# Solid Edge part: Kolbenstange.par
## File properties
Username: bmolnar
Dokumentum tartalom típus: 0
Author: bmolnar
Last saved by: bmolnar
Revision: 82
Sűrűség: 0,000 kg/m^3
Pontosság: 0,990
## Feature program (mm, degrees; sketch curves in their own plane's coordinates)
base feature "unnamed BaseFeature 1"
thread "unnamed Thread 1"
sketch for "unnamed Protrusion 1" plane through (0, 0, -18.3) normal (0, 0, -1) x-axis (0, -1, 0)
  circle centre (0, 0) radius 10
extrude "unnamed Protrusion 1" add finite 6.7 along +normal
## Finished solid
Body 1: solid body, 17 faces, 23 edges, 8 vertices.
  Faces by surface: plane 8, cylinder 4, torus 3, cone 2
  Edges by curve: circle 13, line 6, ellipse 2, intersection 2
Bounding box of the edges (mm; curved faces can reach further): 20.000 x 20.000 x 81.000, from (-10, -10, -25) to (10, 10, 56).
Cylindrical faces by radius (mm): R2.9 x1, R4 x1, R5 x1, R10 x1
Conical faces (half-angle, radius in mm at the cone's reference point): 20 deg R3.5 x1, 60 deg R3.55 x1
Toroidal faces (ring radius, tube radius in mm): R3.3 r0.4 x2, R3.8 r1.2 x1
Planar faces by outward normal: +x 1, +z 3, -x 1, -z 1, oblique 2
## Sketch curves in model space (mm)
circle centre (0, 0, -18.3) radius 10
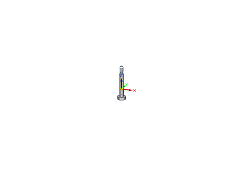
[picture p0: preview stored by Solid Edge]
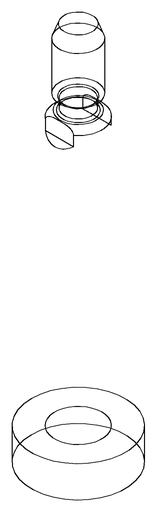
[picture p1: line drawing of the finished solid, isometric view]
